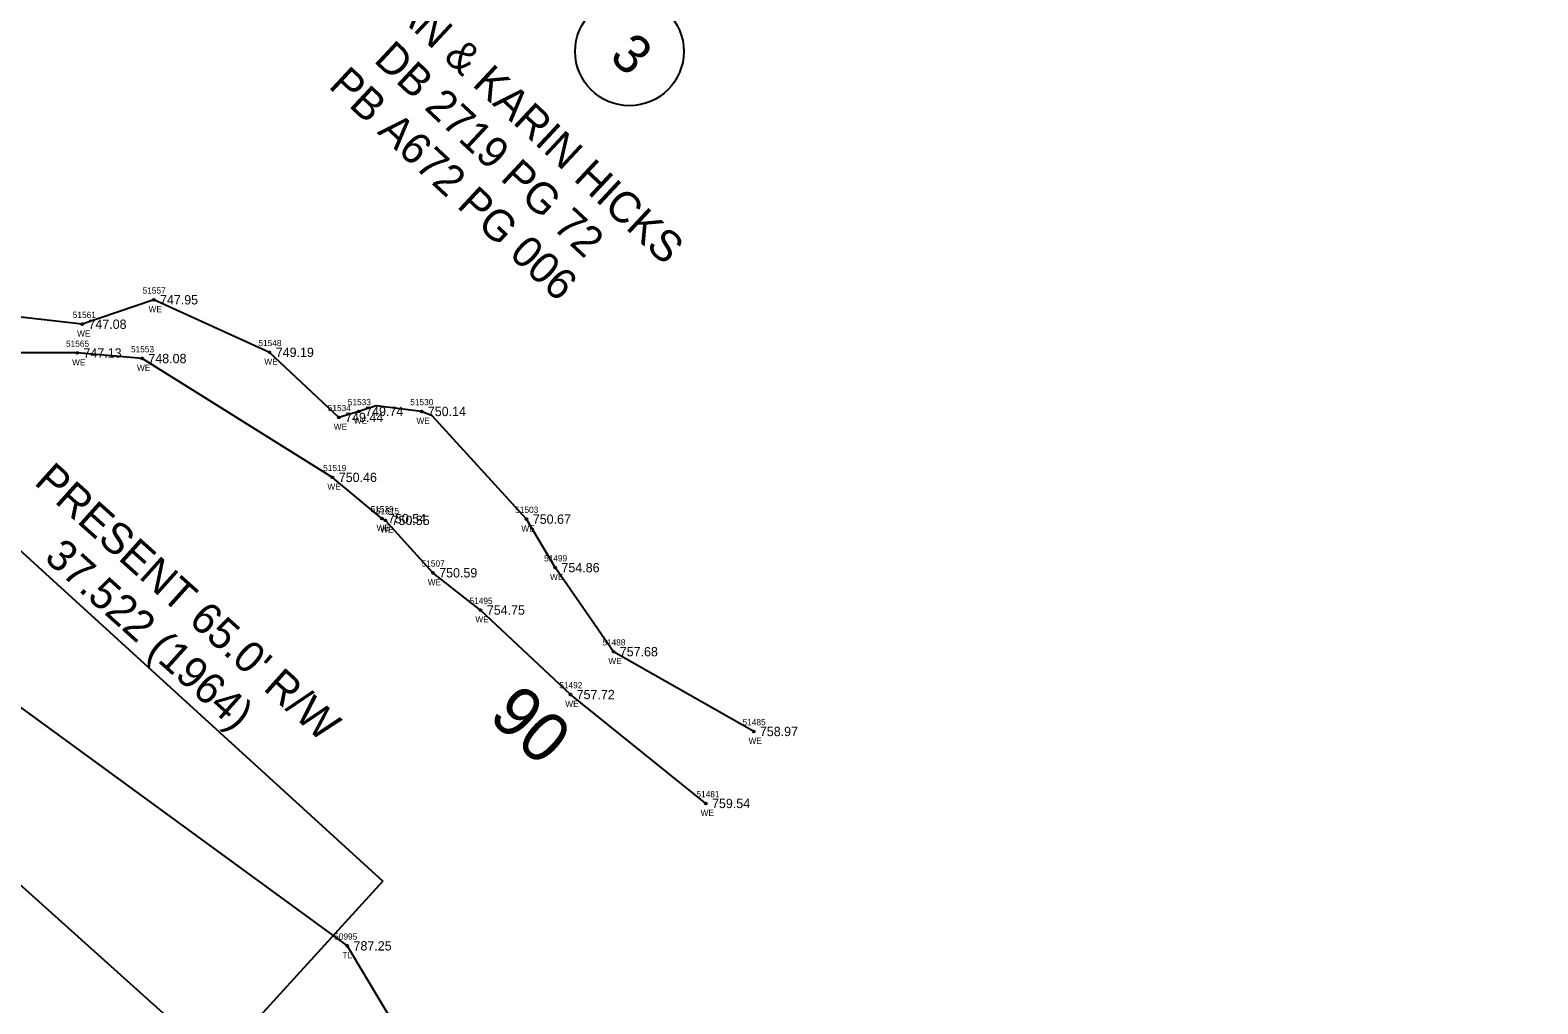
# Model space of a CAD drawing. Extents: x 1378245 to 1381654, y 996521 to 1000567.
# Drawn here: x 1379990.7 to 1380233.5, y 998696.6 to 998853.4 of the extents above; entities that cross this region are included whole.
import ezdxf

# ---------------------------------------------------------------- set-up
doc = ezdxf.new("R2010")
doc.units = 0
for name, color, linetype in [('RD_EX_DV_TX_Prop(Owner ID)', 7, 'Continuous'), ('RD_EX_H2O', 7, 'Continuous'), ('RD_EX_H2O_txCode', 7, 'Continuous'), ('RD_EX_RW', 7, 'Continuous'), ('RD_EX_RW_TX', 7, 'Continuous'), ('RD_EX_SU_Elec', 7, 'Continuous'), ('RD_EX_TX_H2O_ELEV', 7, 'Continuous'), ('RD_EX_TX_VEG_ELEV', 7, 'Continuous'), ('RD_EX_VEG', 7, 'Continuous'), ('RD_EX_VEG_txCode', 7, 'Continuous'), ('RD_HC_TX_Sta50', 7, 'Continuous'), ('RD_SMD_Locator', 7, 'Continuous')]:
    doc.layers.add(name, color=color, linetype=linetype)

msp = doc.modelspace()

# ---------------------------------------------------------------- linework, layer by layer
at = {"layer": 'RD_EX_DV_TX_Prop(Owner ID)'}
msp.add_circle((1380087.19, 998849.95), 8.75, dxfattribs=at)
at = {"layer": 'RD_EX_H2O'}
for points in [[(1380099.49, 998728.85), (1380077.69, 998746.39), (1380063.22, 998759.99), (1380055.55, 998765.99), (1380047.88, 998774.43), (1380047.3, 998774.72), (1380039.38, 998781.36), (1380008.71, 998800.49), (1379998.26, 998801.39), (1379975.29, 998801.51), (1379998.26, 998801.39), (1379975.29, 998801.51), (1379924.85, 998829.3), (1379911.99, 998838.17), (1379905.66, 998841.81), (1379901.08, 998848.93), (1379897.44, 998858.7)], [(1380107.2, 998740.44), (1380084.63, 998753.29), (1380075.24, 998766.82), (1380070.62, 998774.63), (1380055.42, 998791.26), (1380053.72, 998791.97), (1380046.41, 998792.89), (1380043.63, 998791.98), (1380040.4, 998791.02), (1380029.23, 998801.49), (1380010.58, 998809.95), (1379999.06, 998806.02), (1379976.33, 998808.61), (1379928.89, 998834.28), (1379918.79, 998846.24), (1379910.28, 998856.59)]]:
    msp.add_lwpolyline(points, dxfattribs=at)
at = {"layer": 'RD_EX_RW'}
for p, q in [((1379825.73, 998918.4), (1380047.49, 998716.36)), ((1380047.49, 998716.36), (1380025.94, 998692.71))]:
    msp.add_line(p, q, dxfattribs=at)
at = {"layer": 'RD_EX_SU_Elec'}
msp.add_lwpolyline([(1378514.25, 999944.12), (1378777.7, 999831.22), (1379190.17, 999461.05), (1379403.33, 999174.04), (1379756.94, 998924.25), (1380051.16, 998659.97), (1380327.91, 998390.65), (1380546.23, 998058.37)], dxfattribs=at)
at = {"layer": 'RD_EX_VEG'}
msp.add_lwpolyline([(1379745.61, 998947.42), (1379774.57, 998940.6), (1379816.01, 998901.98), (1379842.25, 998875.07), (1379890.91, 998833.28), (1379928.8, 998787.62), (1379978.22, 998752.26), (1380041.75, 998705.92), (1380067.2, 998663.35), (1380118.8, 998637.22), (1380159.3, 998606.26), (1380204.39, 998555.8), (1380215.44, 998549.46)], dxfattribs=at)
at = {"layer": 'RD_SMD_Locator'}
for centre in [(1380010.58, 998809.95), (1379999.06, 998806.02), (1379998.26, 998801.39), (1380008.71, 998800.49), (1380029.23, 998801.49), (1380043.63, 998791.98), (1380053.72, 998791.97), (1380040.4, 998791.02), (1380039.38, 998781.36), (1380047.3, 998774.72), (1380047.88, 998774.43), (1380070.62, 998774.63), (1380055.55, 998765.99), (1380075.24, 998766.82), (1380063.22, 998759.99), (1380084.63, 998753.29), (1380077.69, 998746.39), (1380107.2, 998740.44), (1380099.49, 998728.85), (1380041.75, 998705.92)]:
    msp.add_circle(centre, 0.15, dxfattribs=at)

# ---------------------------------------------------------------- texts
at = {"layer": 'RD_EX_DV_TX_Prop(Owner ID)'}
for s, height, p in [('DEAN & KARIN HICKS', 5, (1380042.14, 998862.76)), ('DB 2719 PG 72', 5, (1380045.84, 998848.37)), ('3', 6.25, (1380083.76, 998848.87)), ('PB A672 PG 006', 5, (1380038.56, 998844.22))]:
    msp.add_text(s, height=height, rotation=317.0049, dxfattribs=at).set_placement(p)
at = {"layer": 'RD_EX_H2O_txCode'}
for s, p in [('51557', (1380008.78, 998810.95)), ('51561', (1379997.53, 998807.02)), ('WE', (1380009.74, 998807.95)), ('WE', (1379998.23, 998804.02)), ('51565', (1379996.44, 998802.39)), ('51553', (1380006.91, 998801.49)), ('51548', (1380027.43, 998802.49)), ('WE', (1379997.42, 998799.39)), ('WE', (1380007.87, 998798.49)), ('WE', (1380028.39, 998799.49)), ('51534', (1380038.6, 998792.02)), ('51533', (1380041.83, 998792.98)), ('51530', (1380051.89, 998792.97)), ('WE', (1380039.56, 998789.02)), ('WE', (1380042.79, 998789.98)), ('WE', (1380052.89, 998789.97)), ('51519', (1380037.86, 998782.36)), ('WE', (1380038.54, 998779.36)), ('51539', (1380045.5, 998775.72)), ('51515', (1380046.37, 998775.43)), ('51503', (1380068.79, 998775.63)), ('WE', (1380046.46, 998772.72)), ('WE', (1380047.05, 998772.43)), ('WE', (1380069.78, 998772.63)), ('51507', (1380053.72, 998766.99)), ('51499', (1380073.44, 998767.82)), ('WE', (1380074.4, 998764.82)), ('WE', (1380054.71, 998763.99)), ('51495', (1380061.43, 998760.99)), ('WE', (1380062.38, 998757.99)), ('51488', (1380082.83, 998754.29)), ('WE', (1380083.79, 998751.29)), ('51492', (1380075.89, 998747.39)), ('WE', (1380076.85, 998744.39)), ('51485', (1380105.41, 998741.44)), ('WE', (1380106.37, 998738.44)), ('51481', (1380097.98, 998729.85)), ('WE', (1380098.65, 998726.85))]:
    msp.add_text(s, height=1, dxfattribs=at).set_placement(p)
at = {"layer": 'RD_EX_RW_TX'}
for s, p in [("PRESENT 65.0' R/W", (1379991.13, 998780.38)), ('37.522 (1964)', (1379992.76, 998768.17))]:
    msp.add_text(s, height=5, rotation=318.1047, dxfattribs=at).set_placement(p)
at = {"layer": 'RD_EX_TX_H2O_ELEV'}
for s, p in [('747.95', (1380011.58, 998809.2)), ('747.08', (1380000.06, 998805.27)), ('747.13', (1379999.26, 998800.64)), ('749.19', (1380030.23, 998800.74)), ('748.08', (1380009.71, 998799.74)), ('749.74', (1380044.63, 998791.23)), ('750.14', (1380054.72, 998791.22)), ('749.44', (1380041.4, 998790.27)), ('750.46', (1380040.38, 998780.61)), ('750.54', (1380048.3, 998773.97)), ('750.55', (1380048.88, 998773.68)), ('750.67', (1380071.62, 998773.88)), ('750.59', (1380056.55, 998765.24)), ('754.86', (1380076.24, 998766.07)), ('754.75', (1380064.22, 998759.24)), ('757.68', (1380085.63, 998752.54)), ('757.72', (1380078.69, 998745.64)), ('758.97', (1380108.2, 998739.69)), ('759.54', (1380100.49, 998728.1))]:
    msp.add_text(s, height=1.5, dxfattribs=at).set_placement(p)
at = {"layer": 'RD_EX_TX_VEG_ELEV'}
msp.add_text('787.25', height=1.5, dxfattribs=at).set_placement((1380042.75, 998705.17))
at = {"layer": 'RD_EX_VEG_txCode'}
for s, p in [('50995', (1380039.63, 998706.92)), ('TL', (1380040.98, 998703.92))]:
    msp.add_text(s, height=1, dxfattribs=at).set_placement(p)
at = {"layer": 'RD_HC_TX_Sta50'}
msp.add_text('90', height=8, rotation=317.6642, dxfattribs=at).set_placement((1380064.26, 998742.59))

doc.saveas('drawing.dxf')
